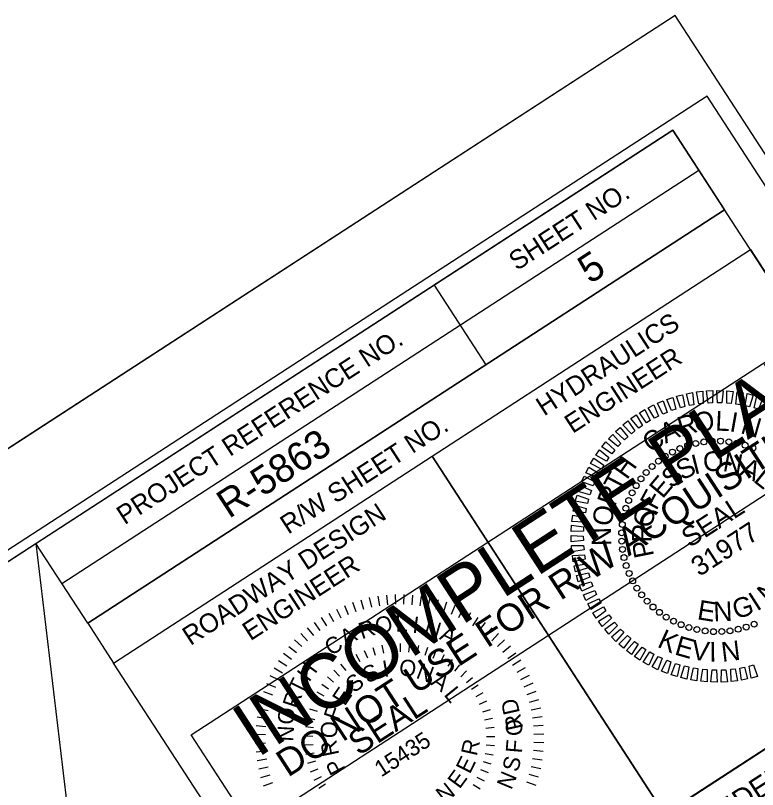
# Model space of a CAD drawing. Extents: x 555170 to 557181, y 503234 to 505074.
# Drawn here: x 556408.1 to 556603.6, y 504870 to 505074 of the extents above; entities that cross this region are included whole.
import ezdxf

# ---------------------------------------------------------------- set-up
doc = ezdxf.new("R2010")
doc.units = 0
for name, color, linetype in [('Default', 7, 'Continuous'), ('Old_Level_21', 7, 'Continuous'), ('Sheet Border Standard 30in CELL', 7, 'Continuous'), ('Sheet Clip Boundary CELL', 7, 'Continuous'), ('Sheet Cutting Line CELL', 7, 'Continuous'), ('Sheet Data Field CELL', 7, 'Continuous'), ('Sheet Plot Border Inside CELL', 7, 'Continuous'), ('Sheet Plot Border Outside CELL', 7, 'Continuous'), ('Sheet Sticker Exception Certification CELL', 7, 'Continuous'), ('Sheet Sticker Incomplete CELL', 7, 'Continuous')]:
    doc.layers.add(name, color=color, linetype=linetype)

msp = doc.modelspace()

# ---------------------------------------------------------------- linework, layer by layer
at = {"layer": 'Default'}
for points in [[(556583.35, 504970.61), (556582.28, 504973.67), (556583.91, 504974.07), (556584.49, 504970.92)], [(556585.73, 504971.2), (556584.88, 504974.32), (556586.53, 504974.61), (556586.89, 504971.43)], [(556588.16, 504971.62), (556587.53, 504974.79), (556589.19, 504974.96), (556589.33, 504971.77)], [(556590.6, 504971.87), (556590.19, 504975.08), (556591.87, 504975.13), (556591.78, 504971.94)], [(556593.06, 504971.95), (556592.88, 504975.18), (556594.55, 504975.11), (556594.24, 504971.93)], [(556595.51, 504971.85), (556595.56, 504975.09), (556597.22, 504974.91), (556596.69, 504971.76)], [(556597.96, 504971.59), (556598.23, 504974.81), (556599.88, 504974.52), (556599.13, 504971.41)], [(556600.38, 504971.16), (556600.87, 504974.35), (556602.49, 504973.94), (556601.53, 504970.9)], [(556602.76, 504970.56), (556603.48, 504973.71), (556605.07, 504973.19), (556603.89, 504970.21)], [(556576.51, 504967.87), (556574.84, 504970.64), (556576.34, 504971.37), (556577.56, 504968.42)], [(556578.72, 504968.95), (556577.25, 504971.82), (556578.8, 504972.44), (556579.81, 504969.41)], [(556581.01, 504969.86), (556579.73, 504972.83), (556581.33, 504973.34), (556582.12, 504970.25)], [(556574.38, 504966.65), (556572.51, 504969.29), (556573.97, 504970.13), (556575.39, 504967.27)], [(556572.34, 504965.28), (556570.29, 504967.79), (556571.68, 504968.72), (556573.3, 504965.97)], [(556568.56, 504962.14), (556566.19, 504964.33), (556567.44, 504965.45), (556569.43, 504962.95)], [(556570.4, 504963.78), (556568.18, 504966.13), (556569.5, 504967.16), (556571.31, 504964.52)], [(556566.85, 504960.37), (556564.33, 504962.4), (556565.5, 504963.6), (556567.65, 504961.24)], [(556565.27, 504958.49), (556562.61, 504960.34), (556563.69, 504961.62), (556566.01, 504959.42)], [(556563.81, 504956.51), (556561.04, 504958.16), (556562.02, 504959.52), (556564.49, 504957.48)], [(556562.51, 504954.43), (556559.62, 504955.89), (556560.51, 504957.3), (556563.11, 504955.45)], [(556561.35, 504952.26), (556558.36, 504953.51), (556559.15, 504954.99), (556561.88, 504953.32)], [(556560.34, 504950.02), (556557.28, 504951.06), (556557.96, 504952.59), (556560.8, 504951.11)], [(556559.49, 504947.71), (556556.36, 504948.54), (556556.94, 504950.11), (556559.87, 504948.83)], [(556558.81, 504945.35), (556555.63, 504945.96), (556556.1, 504947.56), (556559.11, 504946.5)], [(556558.29, 504942.95), (556555.08, 504943.33), (556555.43, 504944.97), (556558.51, 504944.11)], [(556557.94, 504940.51), (556554.71, 504940.67), (556554.95, 504942.33), (556558.08, 504941.69)], [(556557.76, 504938.06), (556554.53, 504937.99), (556554.65, 504939.66), (556557.82, 504939.25)], [(556557.75, 504935.6), (556554.53, 504935.31), (556554.54, 504936.98), (556557.73, 504936.79)], [(556557.92, 504933.15), (556554.73, 504932.63), (556554.61, 504934.3), (556557.81, 504934.33)], [(556558.25, 504930.72), (556555.1, 504929.98), (556554.88, 504931.64), (556558.06, 504931.88)], [(556558.76, 504928.31), (556555.67, 504927.35), (556555.32, 504928.99), (556558.49, 504929.46)], [(556559.43, 504925.95), (556556.41, 504924.78), (556555.96, 504926.39), (556559.08, 504927.08)], [(556560.26, 504923.63), (556557.34, 504922.26), (556556.77, 504923.83), (556559.83, 504924.74)], [(556561.25, 504921.38), (556558.43, 504919.81), (556557.76, 504921.34), (556560.75, 504922.46)], [(556562.4, 504919.21), (556559.7, 504917.44), (556558.91, 504918.92), (556561.82, 504920.24)], [(556563.7, 504917.12), (556561.12, 504915.17), (556560.24, 504916.59), (556563.05, 504918.11)], [(556565.14, 504915.13), (556562.71, 504913), (556561.72, 504914.36), (556564.42, 504916.07)], [(556566.71, 504913.24), (556564.43, 504910.95), (556563.36, 504912.23), (556565.93, 504914.13)], [(556568.41, 504911.47), (556566.3, 504909.02), (556565.14, 504910.23), (556567.57, 504912.3)], [(556570.24, 504909.82), (556568.3, 504907.23), (556567.06, 504908.35), (556569.34, 504910.59)], [(556572.17, 504908.3), (556570.42, 504905.58), (556569.1, 504906.61), (556571.22, 504909.01)], [(556574.2, 504906.92), (556572.65, 504904.08), (556571.26, 504905.02), (556573.21, 504907.56)], [(556576.33, 504905.68), (556574.97, 504902.75), (556573.53, 504903.59), (556575.29, 504906.25)], [(556578.53, 504904.6), (556577.39, 504901.58), (556575.88, 504902.31), (556577.46, 504905.09)], [(556580.81, 504903.67), (556579.88, 504900.58), (556578.33, 504901.21), (556579.7, 504904.09)], [(556583.15, 504902.9), (556582.43, 504899.75), (556580.84, 504900.27), (556582.01, 504903.25)], [(556585.53, 504902.3), (556585.04, 504899.11), (556583.41, 504899.52), (556584.38, 504902.56)], [(556587.95, 504901.87), (556587.68, 504898.65), (556586.03, 504898.94), (556586.78, 504902.05)], [(556600.17, 504902.26), (556601.02, 504899.14), (556599.37, 504898.85), (556599.01, 504902.03)], [(556602.56, 504902.85), (556603.63, 504899.79), (556602, 504899.39), (556601.42, 504902.54)], [(556590.39, 504901.6), (556590.35, 504898.37), (556588.68, 504898.55), (556589.21, 504901.7)], [(556592.85, 504901.51), (556593.03, 504898.28), (556591.36, 504898.35), (556591.67, 504901.53)], [(556595.31, 504901.59), (556595.71, 504898.38), (556594.04, 504898.33), (556594.13, 504901.52)], [(556597.75, 504901.84), (556598.38, 504898.67), (556596.72, 504898.5), (556596.58, 504901.69)]]:
    msp.add_lwpolyline(points, close=True, dxfattribs=at)
for centre in [(556585.24, 504960.64), (556587.36, 504961.22), (556589.51, 504961.62), (556591.7, 504961.82), (556593.89, 504961.84), (556596.07, 504961.66), (556598.23, 504961.29), (556600.35, 504960.74), (556581.21, 504958.94), (556583.19, 504959.88), (556602.42, 504960), (556577.53, 504956.56), (556579.32, 504957.83), (556575.86, 504955.14), (556574.32, 504953.58), (556572.92, 504951.9), (556570.59, 504948.19), (556571.68, 504950.09), (556569.68, 504946.19), (556568.94, 504944.13), (556568.39, 504942.01), (556568.02, 504939.85), (556567.85, 504937.66), (556567.86, 504935.47), (556568.06, 504933.29), (556568.46, 504931.13), (556569.04, 504929.02), (556569.8, 504926.96), (556570.74, 504924.98), (556571.85, 504923.09), (556573.12, 504921.31), (556574.54, 504919.64), (556576.1, 504918.1), (556577.79, 504916.7), (556579.59, 504915.45), (556581.5, 504914.37), (556602.72, 504913.58), (556583.49, 504913.46), (556585.55, 504912.72), (556587.67, 504912.17), (556589.84, 504911.8), (556592.02, 504911.62), (556594.21, 504911.64), (556596.39, 504911.84), (556598.55, 504912.24), (556600.66, 504912.82)]:
    msp.add_circle(centre, 0.777, dxfattribs=at)
at = {"layer": 'Old_Level_21'}
for p, q in [((556501.35, 504920.57), (556501.9, 504918.04)), ((556503.61, 504920.98), (556504, 504918.43)), ((556505.89, 504921.27), (556506.13, 504918.69)), ((556508.18, 504921.41), (556508.26, 504918.82)), ((556510.48, 504921.41), (556510.4, 504918.82)), ((556512.76, 504921.27), (556512.53, 504918.69)), ((556515.05, 504920.99), (556514.66, 504918.43)), ((556517.3, 504920.58), (556516.76, 504918.05)), ((556494.79, 504918.52), (556495.78, 504916.13)), ((556496.93, 504919.34), (556497.78, 504916.89)), ((556499.13, 504920.02), (556499.83, 504917.53)), ((556519.53, 504920.03), (556518.84, 504917.54)), ((556521.73, 504919.35), (556520.88, 504916.91)), ((556523.87, 504918.54), (556522.88, 504916.15)), ((556490.67, 504916.51), (556491.94, 504914.26)), ((556492.7, 504917.58), (556493.83, 504915.25)), ((556525.96, 504917.6), (556524.83, 504915.27)), ((556528, 504916.53), (556526.73, 504914.28)), ((556488.7, 504915.32), (556490.11, 504913.15)), ((556529.96, 504915.35), (556528.56, 504913.17)), ((556485.01, 504912.6), (556486.67, 504910.61)), ((556486.81, 504914.02), (556488.35, 504911.93)), ((556531.85, 504914.05), (556530.32, 504911.96)), ((556533.66, 504912.63), (556532, 504910.64)), ((556483.29, 504911.08), (556485.07, 504909.19)), ((556535.38, 504911.11), (556533.6, 504909.23)), ((556481.67, 504909.46), (556483.56, 504907.68)), ((556507.07, 504908.37), (556507.27, 504906.22)), ((556509.49, 504908.47), (556509.48, 504906.31)), ((556511.91, 504908.34), (556511.69, 504906.19)), ((556537, 504909.49), (556535.12, 504907.71)), ((556480.15, 504907.74), (556482.14, 504906.08)), ((556500.03, 504906.67), (556500.84, 504904.67)), ((556502.32, 504907.46), (556502.93, 504905.39)), ((556504.67, 504908.03), (556505.08, 504905.91)), ((556514.3, 504907.98), (556513.87, 504905.86)), ((556516.64, 504907.39), (556516.01, 504905.32)), ((556518.92, 504906.57), (556518.1, 504904.57)), ((556538.52, 504907.77), (556536.54, 504906.11)), ((556478.74, 504905.93), (556480.83, 504904.39)), ((556495.74, 504904.45), (556496.92, 504902.64)), ((556496.92, 504902.64), (556495.74, 504904.45)), ((556497.84, 504905.66), (556498.83, 504903.75)), ((556521.11, 504905.54), (556520.1, 504903.63)), ((556523.19, 504904.3), (556522, 504902.5)), ((556539.94, 504905.97), (556537.85, 504904.43)), ((556541.25, 504904.08), (556539.07, 504902.67)), ((556476.25, 504902.07), (556478.5, 504900.8)), ((556477.44, 504904.04), (556479.61, 504902.63)), ((556493.78, 504903.04), (556495.12, 504901.35)), ((556525.14, 504902.87), (556523.77, 504901.19)), ((556542.43, 504902.11), (556540.18, 504900.84)), ((556475.18, 504900.04), (556477.51, 504898.91)), ((556491.96, 504901.44), (556493.46, 504899.89)), ((556526.94, 504901.25), (556525.42, 504899.72)), ((556543.5, 504900.08), (556541.18, 504898.95)), ((556474.24, 504897.95), (556476.63, 504896.96)), ((556490.3, 504899.68), (556491.94, 504898.28)), ((556528.58, 504899.47), (556526.92, 504898.09)), ((556544.45, 504897.99), (556542.06, 504897)), ((556488.82, 504897.77), (556490.59, 504896.53)), ((556530.04, 504897.54), (556528.26, 504896.33)), ((556473.43, 504895.8), (556475.88, 504894.96)), ((556487.53, 504895.72), (556489.41, 504894.66)), ((556531.3, 504895.48), (556529.41, 504894.44)), ((556545.26, 504895.85), (556542.82, 504895)), ((556472.75, 504893.61), (556475.24, 504892.91)), ((556486.45, 504893.55), (556488.42, 504892.68)), ((556530.35, 504892.52), (556532.33, 504893.38)), ((556545.95, 504893.65), (556543.45, 504892.95)), ((556472.2, 504891.38), (556474.73, 504890.84)), ((556485.58, 504891.29), (556487.63, 504890.62)), ((556533.21, 504891.04), (556531.16, 504890.38)), ((556546.5, 504891.43), (556543.96, 504890.88)), ((556471.79, 504889.12), (556474.35, 504888.73)), ((556484.93, 504888.96), (556487.04, 504888.49)), ((556533.83, 504888.7), (556531.72, 504888.24)), ((556546.91, 504889.17), (556544.35, 504888.78)), ((556471.51, 504886.84), (556474.09, 504886.61)), ((556484.51, 504886.58), (556486.65, 504886.31)), ((556534.22, 504886.31), (556532.08, 504886.07)), ((556547.19, 504886.89), (556544.61, 504886.66)), ((556471.38, 504884.55), (556473.96, 504884.48)), ((556484.32, 504884.17), (556486.48, 504884.1)), ((556534.39, 504883.9), (556532.23, 504883.86)), ((556547.33, 504884.6), (556544.74, 504884.52)), ((556471.38, 504882.26), (556473.96, 504882.34)), ((556484.37, 504881.75), (556486.52, 504881.89)), ((556534.32, 504881.48), (556532.17, 504881.65)), ((556547.33, 504882.3), (556544.74, 504882.38)), ((556471.52, 504879.97), (556474.1, 504880.2)), ((556484.65, 504879.35), (556486.78, 504879.7)), ((556547.19, 504880.02), (556544.61, 504880.25)), ((556471.8, 504877.69), (556474.35, 504878.08)), ((556485.16, 504876.98), (556487.24, 504877.54)), ((556534.01, 504879.08), (556531.89, 504879.45)), ((556546.92, 504877.74), (556544.36, 504878.12)), ((556472.21, 504875.43), (556474.74, 504875.97)), ((556533.48, 504876.72), (556531.4, 504877.3)), ((556546.5, 504875.48), (556543.97, 504876.02)), ((556472.76, 504873.2), (556475.26, 504873.9)), ((556485.89, 504874.68), (556487.91, 504875.43)), ((556532.72, 504874.42), (556530.7, 504875.2)), ((556545.96, 504873.25), (556543.46, 504873.94)), ((556473.44, 504871.01), (556475.89, 504871.86)), ((556486.85, 504872.45), (556488.78, 504873.4)), ((556488.01, 504870.33), (556489.85, 504871.46)), ((556531.74, 504872.21), (556529.81, 504873.18)), ((556545.27, 504871.06), (556542.83, 504871.9)), ((556530.55, 504870.1), (556528.72, 504871.25))]:
    msp.add_line(p, q, dxfattribs=at)
at = {"layer": 'Sheet Border Standard 30in CELL'}
for p, q in [((556420.36, 504924.31), (556588.13, 505033.27)), ((556427.17, 504913.83), (556594.94, 505022.78)), ((556427.17, 504913.83), (556594.94, 505022.78)), ((556518.43, 505002.9), (556532.04, 504981.93)), ((556517.88, 504957.83), (556579.13, 504863.53)), ((556427.17, 504913.83), (556433.97, 504903.34))]:
    msp.add_line(p, q, dxfattribs=at)
for points in [[(556581.3, 505043.79), (555323.3, 504226.82), (555895.18, 503346.22), (557153.18, 504163.19)], [(556413.52, 504934.83), (556581.3, 505043.79), (556594.94, 505022.78), (556427.17, 504913.83)], [(556517.88, 504957.83), (556601.75, 505012.3), (556663.02, 504917.95), (556579.16, 504863.48)], [(556433.97, 504903.34), (556517.88, 504957.83), (556579.16, 504863.48), (556495.25, 504808.99)]]:
    msp.add_lwpolyline(points, close=True, dxfattribs=at)
at = {"layer": 'Sheet Clip Boundary CELL'}
msp.add_lwpolyline([(555838.52, 503433.47), (555757.63, 503602.94), (555641.38, 503854.94), (555665.07, 503867.43), (555636.39, 503915.75), (555617.07, 503908.99), (555456.45, 504257.61), (555437.06, 504299.18), (556413.52, 504934.83), (556427.07, 504820.42), (556498.53, 504667.56), (556631.84, 504743.04), (556936.88, 504379.27), (557153.18, 504163.19), (555896.02, 503346.77)], close=True, dxfattribs=at)
at = {"layer": 'Sheet Cutting Line CELL'}
msp.add_line((556581.94, 505074.02), (555169.63, 504156.83), dxfattribs=at)
at = {"layer": 'Sheet Plot Border Inside CELL'}
msp.add_lwpolyline([(556590.39, 505052.74), (555192.76, 504145.08), (555767.42, 503260.21), (557165.05, 504167.86)], close=True, dxfattribs=at)
at = {"layer": 'Sheet Plot Border Outside CELL'}
msp.add_lwpolyline([(556581.94, 505074.02), (555169.63, 504156.83), (555768.74, 503234.3), (557181.05, 504151.49)], close=True, dxfattribs=at)
at = {"layer": 'Sheet Sticker Exception Certification CELL'}
msp.add_line((556495.25, 504808.99), (556663.01, 504917.94), dxfattribs=at)
at = {"layer": 'Sheet Sticker Incomplete CELL'}
msp.add_lwpolyline([(556470.36, 504859.78), (556454.37, 504884.41), (556608.47, 504984.49), (556624.47, 504959.85)], close=True, dxfattribs=at)

# ---------------------------------------------------------------- texts
at = {"layer": 'Default'}
for s, height, rotation, p in [('O', 5.18, 8.0709, (556587.25, 504964.05)), ('L', 5.18, 357.3457, (556592.43, 504964.63)), ('I', 5.18, 349.8806, (556596.06, 504964.46)), ('R', 5.18, 16.2795, (556583.41, 504962.95)), ('N', 5.18, 343.9406, (556598.91, 504963.99)), ('A', 5.18, 25.327, (556579.4, 504961.12)), ('C', 5.18, 34.8321, (556575.56, 504958.55)), ('O', 5.18, 5.4206, (556589.52, 504953.71)), ('H', 5.18, 54.4713, (556569.24, 504951.44)), ('S', 5.18, 26.135, (556583.74, 504951.4)), ('I', 5.18, 14.1761, (556586.98, 504952.99)), ('N', 5.18, 349.6118, (556594.28, 504954)), ('S', 5.18, 38.094, (556580.9, 504949.17)), ('A', 5.18, 334.5618, (556598.72, 504953.06)), ('T', 5.18, 62.2605, (556567.46, 504948.09)), ('L', 5.18, 321.2259, (556602.33, 504951.29)), ('E', 5.18, 49.8562, (556578.62, 504946.45)), ('R', 5.18, 70.4692, (556566.1, 504944.33)), ('F', 5.18, 61.5341, (556576.95, 504943.35)), ('SEAL', 5.181, 32.8702, (556585.75, 504933.62)), ('O', 5.18, 81.1943, (556565.16, 504939.2)), ('O', 5.18, 77.3429, (556575.75, 504938.74)), ('R', 5.18, 89.4424, (556575.71, 504935.08)), ('31977', 5.181, 32.8702, (556588.29, 504926)), ('N', 5.18, 91.4048, (556565.16, 504934.23)), ('P', 5.18, 101.2046, (556576.41, 504931.6)), ('N', 5.18, 41.3387, (556606.39, 504918.71)), ('G', 5.18, 17.5332, (556597.97, 504914.82)), ('I', 5.18, 32.5832, (556603.49, 504916.87)), ('E', 5.18, 350.7209, (556587.55, 504914.91)), ('N', 5.18, 2.4831, (556592.11, 504914.27)), ('K', 5.18, 335.484, (556576.97, 504907.72)), ('E', 5.18, 344.1884, (556581.54, 504905.64)), ('V', 5.18, 352.1682, (556585.97, 504904.35)), ('I', 5.18, 0.8535, (556590.94, 504903.67)), ('N', 5.18, 6.7935, (556594.37, 504903.64))]:
    msp.add_text(s, height=height, rotation=rotation, dxfattribs=at).set_placement(p)
at = {"layer": 'Old_Level_21'}
for s, height, rotation, p in [('R', 4.31, 18.2685, (556499.37, 504909.59)), ('O', 4.31, 15.2117, (556503.55, 504910.81)), ('L', 4.31, 2.0754, (556508.27, 504911.59)), ('I', 4.31, 352.4999, (556512.55, 504911.37)), ('N', 4.31, 343.2055, (556515.47, 504910.84)), ('A', 4.31, 30.2778, (556495.18, 504907.64)), ('A', 4.31, 333.4379, (556519.59, 504909.72)), ('C', 4.31, 30.2778, (556491.18, 504905.15)), ('I', 4.31, 9.9765, (556505.23, 504899.61)), ('O', 4.31, 354.6802, (556509.06, 504900.09)), ('H', 4.31, 53.9885, (556485.48, 504898.16)), ('S', 4.31, 25.2727, (556500.87, 504897.9)), ('N', 4.31, 339.384, (556513.42, 504899.47)), ('S', 4.31, 40.569, (556497.45, 504895.26)), ('A', 4.31, 324.0877, (556517.32, 504897.79)), ('T', 4.31, 63.4204, (556483.59, 504894.69)), ('E', 4.31, 55.8652, (556494.86, 504891.82)), ('L', 4.31, 308.7915, (556520.82, 504894.97)), ('R', 4.31, 71.5814, (556482.47, 504891.09)), ('SEAL', 6.474, 32.9208, (556498.56, 504878.76)), ('F', 4.31, 71.1614, (556493.29, 504887.89)), (' RD', 4.312, 102.5933, (556542.3, 504884.62)), ('O', 4.31, 84.6381, (556481.42, 504886.95)), ('O', 4.31, 86.4577, (556492.77, 504883.41)), ('O ', 4.312, 93.9205, (556541.79, 504884.26)), ('N', 4.31, 86.5976, (556481.32, 504882.55)), ('15435', 4.312, 32.9208, (556504.5, 504873.15)), ('R', 4.31, 101.7539, (556493.44, 504879.24)), ('R', 4.31, 77.4857, (556529.65, 504878.66)), ('F', 4.31, 85.1279, (556541.55, 504879.46)), ('E', 4.31, 63.7146, (556527.83, 504873.91)), ('S', 4.31, 76.2453, (556540.52, 504874.44)), ('P', 4.31, 117.0502, (556495.22, 504875.29)), ('E', 4.31, 53.7288, (556525.12, 504869.96)), ('N', 4.31, 67.3626, (556538.76, 504869.73)), ('N', 4.31, 38.3367, (556521.06, 504866.18))]:
    msp.add_text(s, height=height, rotation=rotation, dxfattribs=at).set_placement(p)
at = {"layer": 'Sheet Border Standard 30in CELL'}
for s, height, p in [('SHEET NO.', 5, (556540.22, 505006.62)), ('HYDRAULICS', 5, (556547.4, 504968.3)), ('PROJECT REFERENCE NO.', 5.0001, (556436.88, 504939.63)), ('ENGINEER', 5, (556554.91, 504963.7)), ('R/W SHEET NO.', 5.0001, (556479.98, 504937.16)), ('ROADWAY DESIGN', 5.0001, (556454.22, 504907.79)), ('ENGINEER', 5, (556470.03, 504909.05))]:
    msp.add_text(s, height=height, rotation=33.0007, dxfattribs=at).set_placement(p)
at = {"layer": 'Sheet Data Field CELL'}
for s, p in [('5', (556559.48, 505003.09)), ('R-5863', (556464.37, 504941.27))]:
    msp.add_text(s, height=7.5, rotation=33.0007, dxfattribs=at).set_placement(p)
at = {"layer": 'Sheet Sticker Exception Certification CELL'}
for s, p in [('DOCUMENT NOT CONSIDERED FINAL', (556527.64, 504817.69)), ('UNLESS ALL SIGNATURES COMPLETED', (556533.17, 504810.79))]:
    msp.add_text(s, height=5.5, rotation=33.0007, dxfattribs=at).set_placement(p)
at = {"layer": 'Sheet Sticker Incomplete CELL'}
for s, height, p in [('INCOMPLETE PLANS', 14.4, (556471.79, 504878.16)), ('DO NOT USE FOR R/W ACQUISITION', 7.2, (556479.92, 504873.08))]:
    msp.add_text(s, height=height, rotation=33.0007, dxfattribs=at).set_placement(p)

doc.saveas('drawing.dxf')
